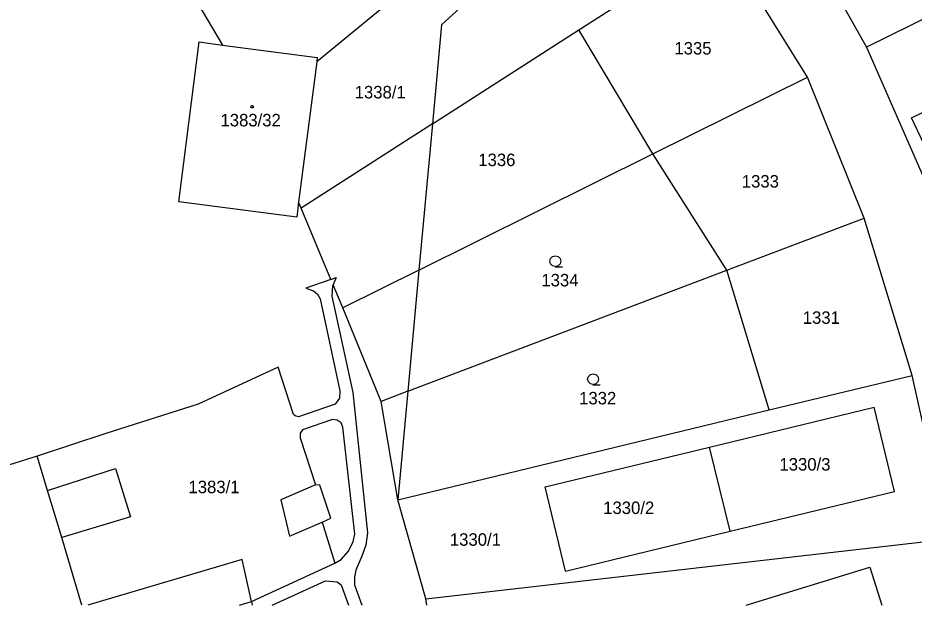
# Model space of a CAD drawing. Extents: x -621797 to -620972, y -1175539 to -1174697.
# Drawn here: x -621620.7 to -621498.7, y -1175532.9 to -1175452.9 of the extents above; entities that cross this region are included whole.
import ezdxf

# ---------------------------------------------------------------- set-up
doc = ezdxf.new("R2010")
doc.units = 0
for name, color, linetype in [('Rozvod plynu EON', 7, 'Continuous'), ('SDEL EON', 7, 'Continuous'), ('SDEL EON - popis', 7, 'Continuous'), ('Silnoproud EON', 7, 'Continuous'), ('Silnoproud EON - popis', 7, 'Continuous')]:
    doc.layers.add(name, color=color, linetype=linetype)

msp = doc.modelspace()

# ---------------------------------------------------------------- linework, layer by layer
at = {"layer": 'Rozvod plynu EON'}
msp.add_lwpolyline([(-621588.69, -1175464.83), (-621588.6, -1175464.98), (-621588.69, -1175465.13), (-621588.87, -1175465.13), (-621588.96, -1175464.98), (-621588.87, -1175464.83)], close=True, dxfattribs=at)
at = {"layer": 'SDEL EON'}
for points in [[(-621547.51, -1175486.75), (-621547.89, -1175486.65), (-621548.16, -1175486.38), (-621548.26, -1175486.01), (-621548.16, -1175485.64), (-621547.89, -1175485.37), (-621547.52, -1175485.27), (-621547.15, -1175485.37), (-621546.88, -1175485.64), (-621546.78, -1175486.02), (-621546.88, -1175486.4), (-621547.15, -1175486.67), (-621547.53, -1175486.77), (-621546.53, -1175486.77)], [(-621542.37, -1175502.82), (-621542.75, -1175502.72), (-621543.02, -1175502.45), (-621543.12, -1175502.08), (-621543.02, -1175501.71), (-621542.75, -1175501.44), (-621542.38, -1175501.34), (-621542.01, -1175501.44), (-621541.74, -1175501.71), (-621541.64, -1175502.09), (-621541.74, -1175502.47), (-621542.01, -1175502.74), (-621542.39, -1175502.84), (-621541.39, -1175502.84)]]:
    msp.add_lwpolyline(points, dxfattribs=at)
at = {"layer": 'SDEL EON - popis'}
for p, q in [((-621538.22, -1175424.5), (-621580, -1175458.85)), ((-621564.25, -1175467.31), (-621582.13, -1175478.78)), ((-621566.08, -1175487.23), (-621576.45, -1175492.38)), ((-621578.07, -1175488.5), (-621581.51, -1175489.69)), ((-621577.84, -1175489.39), (-621577.94, -1175490.77)), ((-621577.77, -1175489.22), (-621577.84, -1175489.39)), ((-621581.51, -1175489.69), (-621580.46, -1175490.06)), ((-621580.46, -1175490.06), (-621579.9, -1175490.49)), ((-621579.9, -1175490.49), (-621579.54, -1175491.16)), ((-621579.54, -1175491.16), (-621576.85, -1175503.69)), ((-621577.94, -1175490.77), (-621575.1, -1175503.89)), ((-621585.24, -1175500.47), (-621596.15, -1175505.47)), ((-621583.15, -1175506.9), (-621585.24, -1175500.47)), ((-621576.85, -1175503.69), (-621576.9, -1175504.65)), ((-621575.1, -1175503.89), (-621573.09, -1175523.02)), ((-621567.6, -1175503.74), (-621571.25, -1175505.13)), ((-621576.9, -1175504.65), (-621577.49, -1175505.48)), ((-621596.15, -1175505.47), (-621608.72, -1175509.49)), ((-621577.49, -1175505.48), (-621582.48, -1175507.23)), ((-621582.92, -1175507.1), (-621583.15, -1175506.9)), ((-621582.48, -1175507.23), (-621582.92, -1175507.1)), ((-621577.86, -1175507.58), (-621581.92, -1175508.97)), ((-621577.21, -1175507.69), (-621577.86, -1175507.58)), ((-621576.69, -1175508.05), (-621577.21, -1175507.69)), ((-621576.45, -1175508.64), (-621576.69, -1175508.05)), ((-621574.8, -1175523.2), (-621576.45, -1175508.64)), ((-621608.72, -1175509.49), (-621618.06, -1175512.55)), ((-621581.92, -1175508.97), (-621582.28, -1175509.46)), ((-621582.28, -1175509.46), (-621582.25, -1175510.08)), ((-621582.25, -1175510.08), (-621580.18, -1175516.46)), ((-621616.65, -1175517.26), (-621607.41, -1175514.26)), ((-621607.41, -1175514.26), (-621605.35, -1175520.81)), ((-621580.18, -1175516.46), (-621584.9, -1175518.54)), ((-621579.59, -1175516.54), (-621580.18, -1175516.46)), ((-621578.09, -1175521.01), (-621579.59, -1175516.54)), ((-621584.9, -1175518.54), (-621583.71, -1175523.48)), ((-621605.35, -1175520.81), (-621614.73, -1175523.65)), ((-621579.26, -1175521.58), (-621578.09, -1175521.01)), ((-621583.71, -1175523.48), (-621579.26, -1175521.58)), ((-621579.26, -1175521.58), (-621577.53, -1175527.12)), ((-621575.03, -1175524.19), (-621574.8, -1175523.2)), ((-621573.09, -1175523.02), (-621573.3, -1175524.7)), ((-621575.68, -1175525.53), (-621575.03, -1175524.19)), ((-621573.3, -1175524.7), (-621573.88, -1175526.19)), ((-621576.68, -1175526.64), (-621575.68, -1175525.53)), ((-621588.89, -1175532.36), (-621577.53, -1175527.12)), ((-621577.53, -1175527.12), (-621576.68, -1175526.64)), ((-621573.88, -1175526.19), (-621574.66, -1175528.1)), ((-621574.66, -1175528.1), (-621574.85, -1175529.07)), ((-621586.078, -1175532.85), (-621578.79, -1175529.57)), ((-621578.79, -1175529.57), (-621577.22, -1175529.7)), ((-621574.85, -1175529.07), (-621574.88, -1175530.08)), ((-621577.22, -1175529.7), (-621576.69, -1175530.09)), ((-621576.69, -1175530.09), (-621575.673, -1175532.85)), ((-621574.88, -1175530.08), (-621573.854, -1175532.85))]:
    msp.add_line(p, q, dxfattribs=at)
at = {"layer": 'Silnoproud EON'}
for p, q in [((-621535.21, -1175428.49), (-621563.01, -1175453.81)), ((-621514.93, -1175439.55), (-621505.14, -1175456.86)), ((-621544.32, -1175454.53), (-621524.95, -1175442.09)), ((-621513.2, -1175460.94), (-621524.95, -1175442.09)), ((-621478.69, -1175443.87), (-621505.14, -1175456.86)), ((-621596.31, -1175450.69), (-621592.82, -1175456.58)), ((-621563.01, -1175453.81), (-621564.25, -1175467.31)), ((-621564.25, -1175467.31), (-621544.32, -1175454.53)), ((-621534.25, -1175471.4), (-621544.32, -1175454.53)), ((-621598.8, -1175477.95), (-621595.99, -1175456.16)), ((-621595.99, -1175456.16), (-621592.82, -1175456.58)), ((-621592.82, -1175456.58), (-621579.93, -1175458.29)), ((-621505.14, -1175456.86), (-621497.12, -1175475.22)), ((-621580, -1175458.85), (-621582.47, -1175477.96)), ((-621579.93, -1175458.29), (-621580, -1175458.85)), ((-621534.25, -1175471.4), (-621513.2, -1175460.94)), ((-621505.48, -1175480.15), (-621513.2, -1175460.94)), ((-621499.04, -1175466.5), (-621495.7, -1175464.89)), ((-621564.25, -1175467.31), (-621566.08, -1175487.23)), ((-621497.34, -1175470.03), (-621499.04, -1175466.5)), ((-621566.08, -1175487.23), (-621534.25, -1175471.4)), ((-621524.18, -1175487.25), (-621534.25, -1175471.4)), ((-621582.73, -1175480.01), (-621598.8, -1175477.95)), ((-621582.47, -1175477.96), (-621582.73, -1175480.01)), ((-621582.13, -1175478.78), (-621582.47, -1175477.96)), ((-621578.07, -1175488.5), (-621582.13, -1175478.78)), ((-621524.18, -1175487.25), (-621505.48, -1175480.15)), ((-621498.94, -1175501.58), (-621505.48, -1175480.15)), ((-621566.08, -1175487.23), (-621567.6, -1175503.74)), ((-621567.6, -1175503.74), (-621524.18, -1175487.25)), ((-621518.38, -1175506.28), (-621524.18, -1175487.25)), ((-621578.07, -1175488.5), (-621577.35, -1175488.25)), ((-621577.35, -1175488.25), (-621577.77, -1175489.22)), ((-621576.45, -1175492.38), (-621577.77, -1175489.22)), ((-621571.25, -1175505.13), (-621576.45, -1175492.38)), ((-621518.38, -1175506.28), (-621498.94, -1175501.58)), ((-621493.99, -1175523.82), (-621498.94, -1175501.58)), ((-621567.6, -1175503.74), (-621568.96, -1175518.51)), ((-621568.96, -1175518.51), (-621571.25, -1175505.13)), ((-621568.96, -1175518.51), (-621518.38, -1175506.28)), ((-621526.51, -1175511.33), (-621504.1, -1175505.91)), ((-621501.33, -1175517.38), (-621504.1, -1175505.91)), ((-621548.91, -1175516.75), (-621526.51, -1175511.33)), ((-621523.73, -1175522.8), (-621526.51, -1175511.33)), ((-621618.06, -1175512.55), (-621637.12, -1175518.54)), ((-621616.65, -1175517.26), (-621618.06, -1175512.55)), ((-621614.73, -1175523.65), (-621616.65, -1175517.26)), ((-621546.14, -1175528.22), (-621548.91, -1175516.75)), ((-621523.73, -1175522.8), (-621501.33, -1175517.38)), ((-621565.15, -1175532), (-621568.96, -1175518.51)), ((-621546.14, -1175528.22), (-621523.73, -1175522.8)), ((-621611.966, -1175532.85), (-621614.73, -1175523.65)), ((-621565.15, -1175532), (-621493.99, -1175523.82)), ((-621590.17, -1175526.64), (-621611.157, -1175532.85)), ((-621588.89, -1175532.36), (-621590.17, -1175526.64)), ((-621521.538, -1175532.85), (-621504.71, -1175527.7)), ((-621504.71, -1175527.7), (-621503.075, -1175532.85)), ((-621565.025, -1175532.85), (-621565.15, -1175532)), ((-621590.509, -1175532.85), (-621588.89, -1175532.36)), ((-621588.89, -1175532.36), (-621588.78, -1175532.85))]:
    msp.add_line(p, q, dxfattribs=at)

# ---------------------------------------------------------------- texts
at = {"layer": 'Silnoproud EON - popis'}
for s, p in [('1335', (-621531.307, -1175457.87)), ('1338/1', (-621574.837, -1175463.85)), ('1383/32', (-621593.107, -1175467.66)), ('1336', (-621558.007, -1175473.07)), ('1333', (-621522.127, -1175475.99)), ('1334', (-621549.417, -1175489.45)), ('1331', (-621513.827, -1175494.55)), ('1332', (-621544.277, -1175505.52)), ('1330/3', (-621517.002, -1175514.53)), ('1383/1', (-621597.467, -1175517.61)), ('1330/2', (-621540.999, -1175520.45)), ('1330/1', (-621561.877, -1175524.77))]:
    msp.add_text(s, height=1.7, dxfattribs=at).set_placement(p)

doc.saveas('drawing.dxf')
